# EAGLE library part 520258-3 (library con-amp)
AMP connector
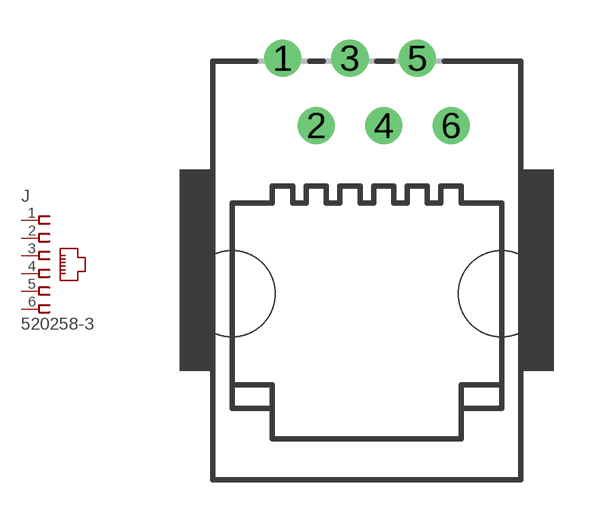
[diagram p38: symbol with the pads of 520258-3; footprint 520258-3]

Designator prefix J

## 520258-3 (MF: TYCO ELECTRONICS; MPN: 5520258-3; OC_FARNELL: 1214651; OC_NEWARK: 42K7227)  [520258-3]
1  1  pas
2  2  pas
3  3  pas
4  4  pas
5  5  pas
6  6  pas

## Footprint 520258-3 (pad centres in mm)
Modular Jack with Panel Stops
drill 0.889 round: 1 -3.175,8.001; 2 -1.905,5.461; 3 -0.635,8.001; 4 0.635,5.461; 5 1.905,8.001; 6 3.175,5.461
hole 3.251 at -5.08,-0.889
hole 3.251 at 5.08,-0.889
